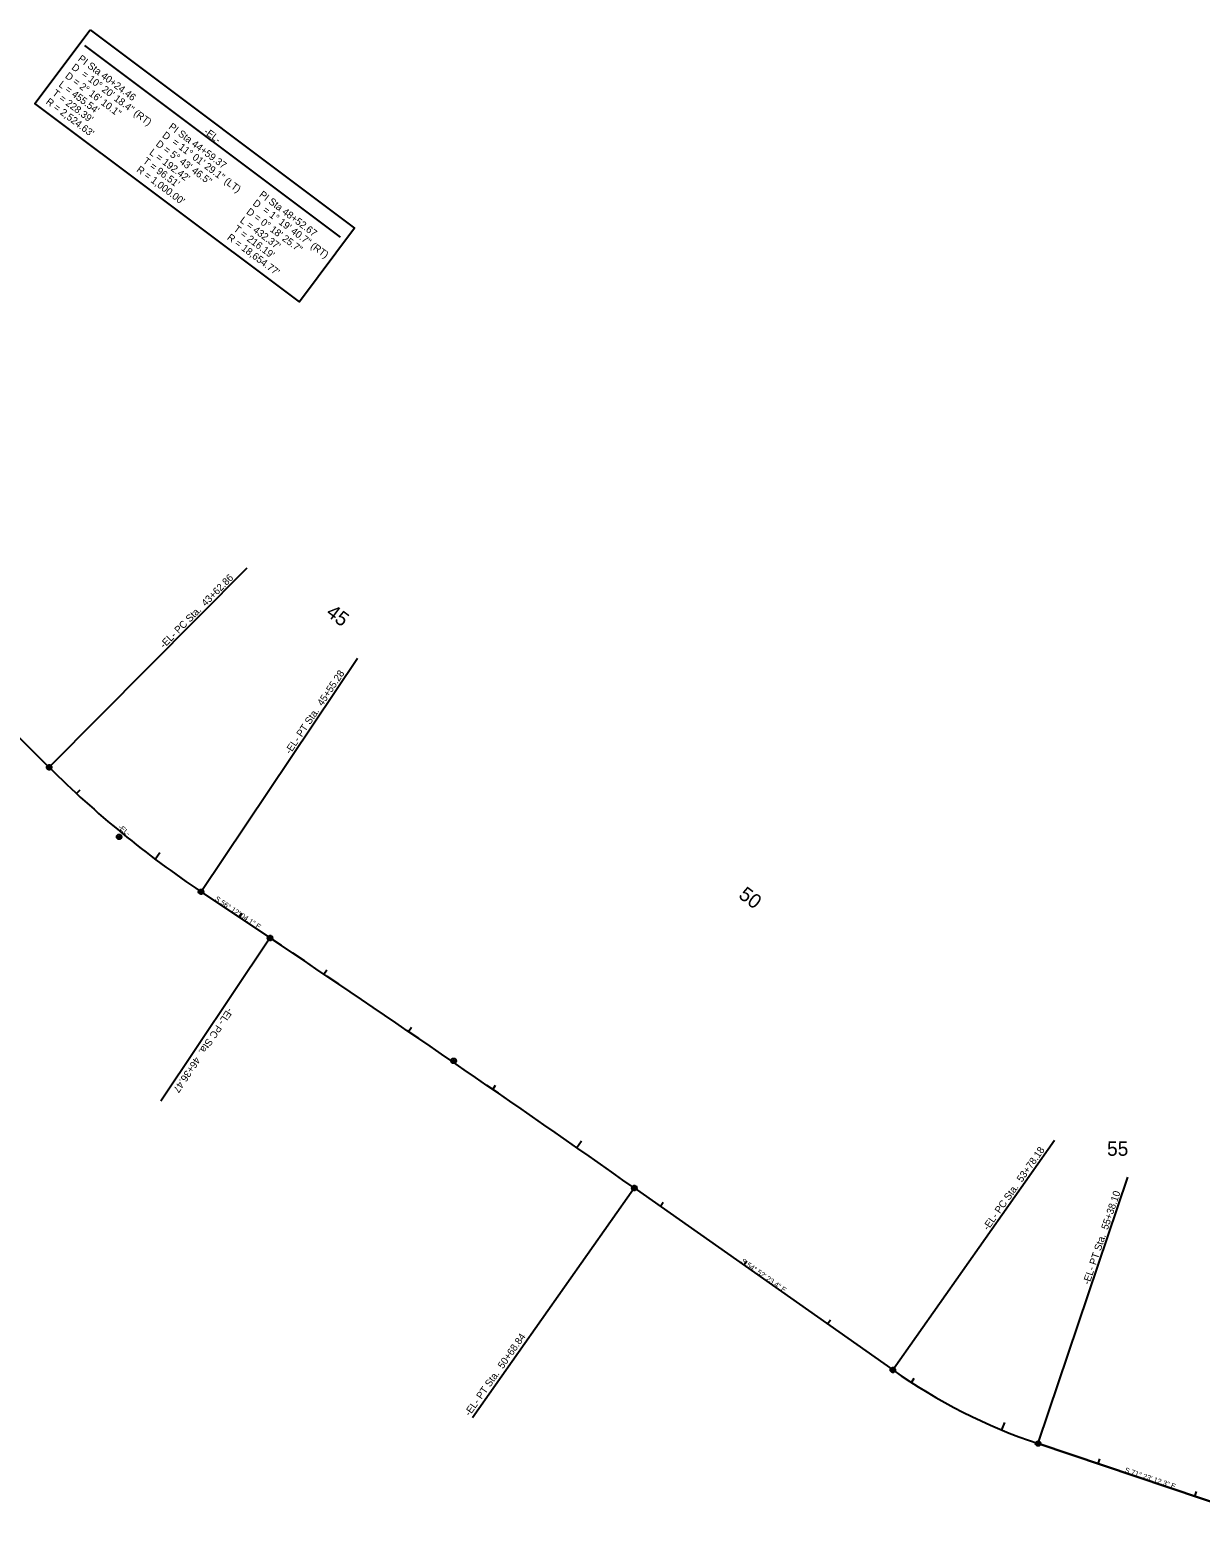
# Model space of a CAD drawing. Extents: x 928071 to 937324, y 684061 to 686812.
# Drawn here: x 930989 to 932135, y 684418 to 685874 of the extents above; entities that cross this region are included whole.
import ezdxf

# ---------------------------------------------------------------- set-up
doc = ezdxf.new("R2010")
doc.units = 0
for name, color, linetype in [('COGO Default Chain', 7, 'Continuous'), ('COGO Default Curve', 7, 'Continuous'), ('Cogo Default Point CELL', 7, 'Continuous'), ('Default', 7, 'Continuous'), ('Exist Horizontal Alignment', 7, 'Continuous'), ('Exist Horizontal Alignment Curve and Spiral Data', 7, 'Continuous'), ('Exist Horizontal Alignment Direction Label', 7, 'Continuous'), ('Exist Horizontal Alignment Station Label', 7, 'Continuous'), ('Exist Horizontal Alignment Tick Label', 7, 'Continuous'), ('Exist Horizontal Alignment Tick Large', 7, 'Continuous'), ('Exist Horizontal Alignment Tick Small', 7, 'Continuous'), ('Prop DSN Text', 7, 'Continuous')]:
    doc.layers.add(name, color=color, linetype=linetype)

msp = doc.modelspace()

# ---------------------------------------------------------------- linework, layer by layer
at = {"layer": 'COGO Default Chain'}
for p, q in [((930929.2, 685230.9), (931008.1, 685152.5)), ((931156.7, 685030.8), (931224.2, 684985.6)), ((931580.7, 684741), (931833.7, 684563)), ((931975.8, 684491), (932192.7, 684417.9))]:
    msp.add_line(p, q, dxfattribs=at)
for centre, radius, start, end in [((931713, 685861.8), 1000, 225.1764, 236.2011), ((920846.9, 669483.6), 18654.8, 54.87317, 56.20114), ((932152.9, 685016.8), 554.9, 234.8732, 251.3867)]:
    msp.add_arc(centre, radius, start, end, dxfattribs=at)
at = {"layer": 'COGO Default Curve'}
for centre, radius, start, end in [((931713, 685861.8), 1000, 225.1764, 236.2011), ((920846.9, 669483.6), 18654.8, 54.87317, 56.20114), ((932152.9, 685016.8), 554.9, 234.8732, 251.3867)]:
    msp.add_arc(centre, radius, start, end, dxfattribs=at)
at = {"layer": 'Cogo Default Point CELL'}
for points in [[(931005.1, 685152.5), (931008.1, 685152.5)], [(931008.1, 685155.5), (931008.1, 685152.5)], [(931008.1, 685152.5), (931011.1, 685152.5)], [(931008.1, 685152.5), (931008.1, 685149.5)], [(931076.5, 685087.5), (931076.5, 685084.5)], [(931073.5, 685084.5), (931076.5, 685084.5)], [(931076.5, 685084.5), (931079.5, 685084.5)], [(931076.5, 685084.5), (931076.5, 685081.5)], [(931153.7, 685030.8), (931156.7, 685030.8)], [(931156.7, 685033.8), (931156.7, 685030.8)], [(931156.7, 685030.8), (931159.7, 685030.8)], [(931156.7, 685030.8), (931156.7, 685027.8)], [(931221.2, 684985.6), (931224.2, 684985.6)], [(931224.2, 684988.6), (931224.2, 684985.6)], [(931224.2, 684985.6), (931227.2, 684985.6)], [(931224.2, 684985.6), (931224.2, 684982.6)], [(931403.9, 684868.4), (931403.9, 684865.4)], [(931400.9, 684865.4), (931403.9, 684865.4)], [(931403.9, 684865.4), (931406.9, 684865.4)], [(931403.9, 684865.4), (931403.9, 684862.4)], [(931577.7, 684741), (931580.7, 684741)], [(931580.7, 684744), (931580.7, 684741)], [(931580.7, 684741), (931583.7, 684741)], [(931580.7, 684741), (931580.7, 684738)], [(931830.7, 684563), (931833.7, 684563)], [(931833.7, 684566), (931833.7, 684563)], [(931833.7, 684563), (931836.7, 684563)], [(931833.7, 684563), (931833.7, 684560)], [(931972.8, 684491), (931975.8, 684491)], [(931975.8, 684494), (931975.8, 684491)], [(931975.8, 684491), (931978.8, 684491)], [(931975.8, 684491), (931975.8, 684488)]]:
    msp.add_lwpolyline(points, dxfattribs=at)
for centre in [(931008.1, 685152.5), (931076.5, 685084.5), (931156.7, 685030.8), (931224.2, 684985.6), (931403.9, 684865.4), (931580.7, 684741), (931833.7, 684563), (931975.8, 684491)]:
    msp.add_circle(centre, 2.34, dxfattribs=at)
at = {"layer": 'Default'}
for p, q in [((931008.1, 685152.5), (930929.2, 685230.9)), ((931224.2, 684985.6), (931156.7, 685030.8)), ((931580.7, 684741), (931833.7, 684563)), ((932192.7, 684417.9), (931975.8, 684491))]:
    msp.add_line(p, q, dxfattribs=at)
msp.add_lwpolyline([(931048.1, 685874), (931306.9, 685680.1), (931253, 685608), (930994.1, 685802)], close=True, dxfattribs=at)
for centre, radius, start, end in [((931713, 685861.8), 1000, 225.1764, 236.2011), ((920846.9, 669483.6), 18654.8, 54.87317, 56.20114), ((932152.9, 685016.8), 554.9, 234.8732, 251.3867)]:
    msp.add_arc(centre, radius, start, end, dxfattribs=at)
at = {"layer": 'Exist Horizontal Alignment'}
for p, q in [((930929.2, 685230.9), (931008.1, 685152.5)), ((931156.7, 685030.8), (931224.2, 684985.6)), ((931580.7, 684741), (931833.7, 684563)), ((931975.8, 684491), (932192.7, 684417.9))]:
    msp.add_line(p, q, dxfattribs=at)
for centre, radius, start, end in [((931713, 685861.8), 1000, 225.1764, 236.2011), ((920846.9, 669483.6), 18654.8, 54.87317, 56.20114), ((932152.9, 685016.8), 554.9, 234.8732, 251.3867)]:
    msp.add_arc(centre, radius, start, end, dxfattribs=at)
at = {"layer": 'Exist Horizontal Alignment Curve and Spiral Data'}
msp.add_line((931042.6, 685858.5), (931292.7, 685671.1), dxfattribs=at)
at = {"layer": 'Exist Horizontal Alignment Station Label'}
for p, q in [((931009.1, 685153.6), (931201.9, 685347.6)), ((931157.6, 685032.1), (931309.7, 685259.3)), ((931223.4, 684984.4), (931117.3, 684825.9)), ((931834.5, 684564.2), (931991.9, 684787.9)), ((931976.3, 684492.4), (932063.6, 684751.6)), ((931579.8, 684739.8), (931422.4, 684516.1))]:
    msp.add_line(p, q, dxfattribs=at)
for centre in [(931008.1, 685152.5), (931156.7, 685030.8), (931224.2, 684985.6), (931580.7, 684741), (931833.7, 684563), (931975.8, 684491)]:
    msp.add_circle(centre, 1.5, dxfattribs=at)
at = {"layer": 'Exist Horizontal Alignment Tick Large'}
for p, q in [((931111.7, 685062.8), (931116.5, 685069.2)), ((931524.3, 684780.5), (931528.9, 684787)), ((931940.2, 684504.4), (931943.3, 684511.7))]:
    msp.add_line(p, q, dxfattribs=at)
at = {"layer": 'Exist Horizontal Alignment Tick Small'}
for p, q in [((931034.9, 685126.8), (931038.3, 685130.5)), ((931193.9, 685005.9), (931196.7, 685010.1)), ((931276.9, 684950.2), (931279.7, 684954.4)), ((931359.7, 684894.1), (931362.5, 684898.2)), ((931442.2, 684837.5), (931445, 684841.6)), ((931606.2, 684723.1), (931609, 684727.1)), ((931688, 684665.5), (931690.8, 684669.6)), ((931769.7, 684608), (931772.6, 684612.1)), ((931851.8, 684550.8), (931854.5, 684555)), ((932034.5, 684471.2), (932036.1, 684475.9)), ((932129.3, 684439.3), (932130.9, 684444))]:
    msp.add_line(p, q, dxfattribs=at)

# ---------------------------------------------------------------- texts
at = {"layer": 'Exist Horizontal Alignment Curve and Spiral Data'}
for s, p in [('PI Sta 40+24.46', (931035.7, 685844.4)), ('D = 2%%d 16\' 10.1"', (931023.1, 685827.6)), ('D', (931029.4, 685836)), ('= 10%%d 20\' 18.4" (RT)', (931039.1, 685829.2)), ("T = 228.39'", (931010.5, 685810.7)), ("L = 455.54'", (931016.8, 685819.1)), ("R = 2,524.63'", (931004.2, 685802.3)), ('D', (931118.1, 685769.5)), ('PI Sta 44+59.37', (931124.4, 685777.9)), ('-EL-', (931158.8, 685773.2)), ("L = 192.42'", (931105.5, 685752.7)), ('D = 5%%d 43\' 46.5"', (931111.8, 685761.1)), ('= 11%%d 01\' 29.1" (LT)', (931127.7, 685762.8)), ("T = 96.51'", (931099.2, 685744.3)), ("R = 1,000.00'", (931092.9, 685735.9)), ('PI Sta 48+52.67', (931213, 685711.5)), ('D = 0%%d 18\' 25.7"', (931200.4, 685694.7)), ('D', (931206.7, 685703.1)), ('= 1%%d 19\' 40.7" (RT)', (931216.4, 685696.3)), ("T = 216.19'", (931187.9, 685677.9)), ("L = 432.37'", (931194.2, 685686.3)), ("R = 18,654.77'", (931181.6, 685669.5))]:
    msp.add_text(s, height=7, rotation=323.1562, dxfattribs=at).set_placement(p)
at = {"layer": 'Exist Horizontal Alignment Direction Label'}
for s, rotation, p in [('S 56%%d 12\' 04.1" E', 326.2011, (931169.8, 685022.7)), ('S 54%%d 52\' 23.4" E', 324.8732, (931684.7, 684668.4)), ('S 71%%d 23\' 12.3" E', 341.3867, (932060.1, 684463.1))]:
    msp.add_text(s, height=5, rotation=rotation, dxfattribs=at).set_placement(p)
at = {"layer": 'Exist Horizontal Alignment Station Label'}
for s, rotation, p in [('-EL- PC Sta.  43+62.86', 45.1764, (931120.5, 685268.5)), ('-EL- PT Sta.  45+55.28', 56.2011, (931244, 685164.8)), ('-EL- PC Sta.  46+36.47', 236.2011, (931183, 684917.9)), ('-EL- PC Sta.  53+78.18', 54.8732, (931926.8, 684698.9)), ('-EL- PT Sta.  55+38.10', 71.3867, (932025.9, 684645.9)), ('-EL- PT Sta.  50+68.84', 54.8732, (931419.5, 684517.2))]:
    msp.add_text(s, height=7, rotation=rotation, dxfattribs=at).set_placement(p)
at = {"layer": 'Exist Horizontal Alignment Tick Label'}
for s, p in [('45', (931278.1, 685301.8)), ('50', (931681.8, 685025.6))]:
    msp.add_text(s, height=14, rotation=323.1561, dxfattribs=at).set_placement(p)
msp.add_text('55', height=14, dxfattribs=at).set_placement((932043.3, 684772.5))
at = {"layer": 'Prop DSN Text'}
msp.add_text('-EL-', height=5, rotation=320.8249, dxfattribs=at).set_placement((931075, 685093.2))

doc.saveas('drawing.dxf')
